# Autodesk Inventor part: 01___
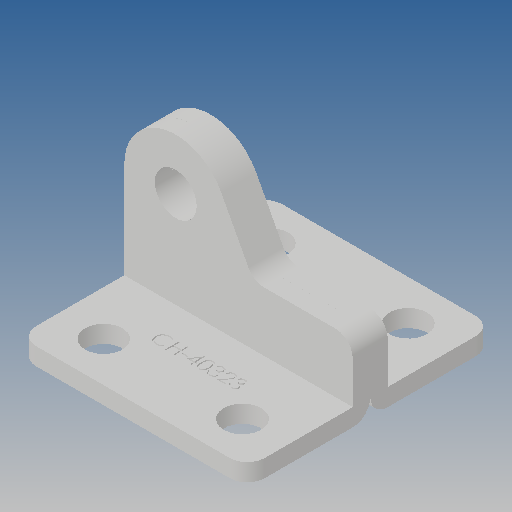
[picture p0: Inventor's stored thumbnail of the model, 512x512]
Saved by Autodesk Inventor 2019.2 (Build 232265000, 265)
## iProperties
Created: 2010-06
Part Number: 01___
Material: Ogólny
Document SubType Name: Modeling
Designer: CADENGINEERING4
Density: 1 g/cm^3
Appearance: Domyślna
Author: CADENGINEERING4
Revision Number: ANY
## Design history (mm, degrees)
feature "NONE"
feature "NONE:1"
node "Bryła1"
node "Bryła2"
